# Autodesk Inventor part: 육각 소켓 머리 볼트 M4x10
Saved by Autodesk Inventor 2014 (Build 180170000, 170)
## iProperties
Created: 2025-06
Part Number: 육각 소켓 머리 볼트 M4x10
Material: 일반
Document SubType Name: Modeling
Designer: dg
Density: 1 g/cm^3
Appearance: 기본값
Author: dg
Author: jhkim
Description: 6각머리 태핑 나사
Creation Date: 2025-05-27
Sending System: Autodesk Inventor 2026
Preprocessor: ST-DEVELOPER v20.1
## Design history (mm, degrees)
node "육각 소켓 머리 볼트 M4x101"
body "Solid1"
node "기준1"
